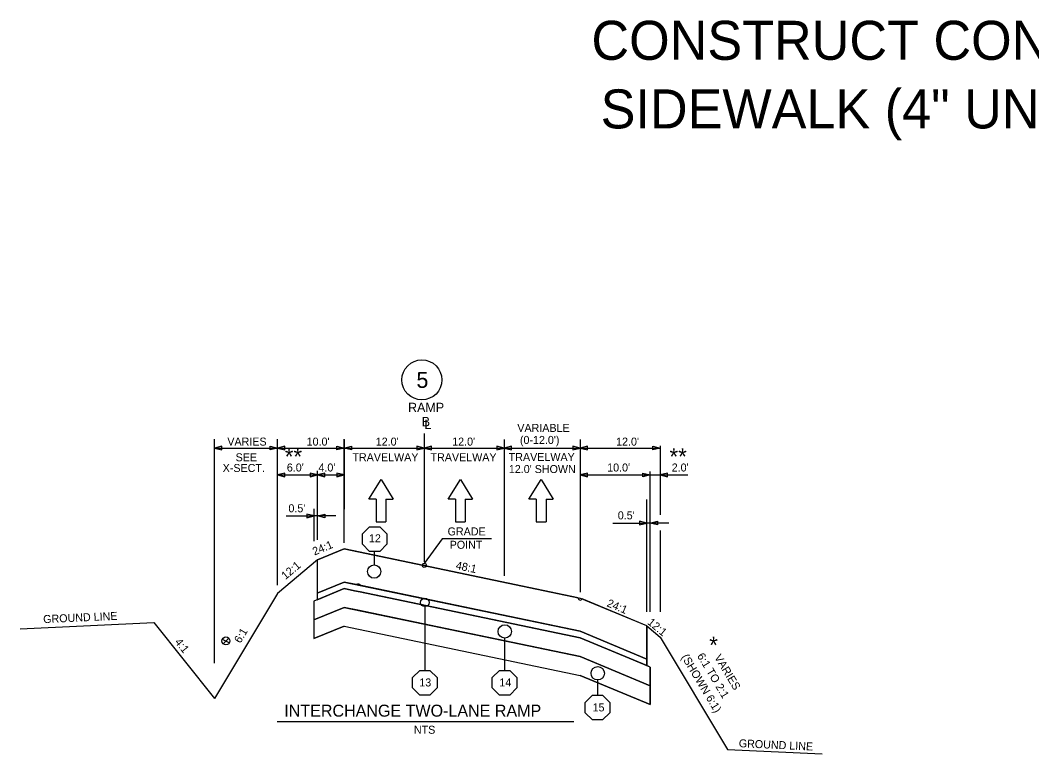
# Model space of a CAD drawing. Extents: x 4932 to 5887, y 4809 to 5473.
# Drawn here: x 5064.4 to 5216, y 5324.2 to 5434.1 of the extents above; entities that cross this region are included whole.
import ezdxf

# ---------------------------------------------------------------- set-up
doc = ezdxf.new("R2010")
doc.units = 0
for name, color, linetype in [('Level 1', 7, 'Continuous'), ('Level 2', 7, 'Continuous'), ('Level 20', 7, 'Continuous'), ('Level 25', 7, 'Continuous'), ('RD_QTY_Miscl_1', 7, 'Continuous'), ('RD_QTY_Miscl_2', 7, 'Continuous'), ('RD_QTY_Miscl_3', 7, 'Continuous'), ('RD_QTY_Miscl_4', 7, 'Continuous'), ('RD_SHT_Typical', 7, 'Continuous'), ('RD_TX_TypSect', 7, 'Continuous'), ('RD_XS_ExGround', 7, 'Continuous'), ('typical_on', 7, 'Continuous')]:
    doc.layers.add(name, color=color, linetype=linetype)

msp = doc.modelspace()

# ---------------------------------------------------------------- linework, layer by layer
at = {"layer": 'Level 2'}
for p, q in [((5108.93, 5350.24), (5108.93, 5350.24)), ((5108.93, 5350.18), (5108.93, 5350.18))]:
    msp.add_line(p, q, dxfattribs=at)
at = {"layer": 'Level 20'}
for p, q in [((5116.67, 5362.36), (5118.49, 5365.27)), ((5118.49, 5365.27), (5120.28, 5362.35)), ((5128.56, 5362.36), (5130.39, 5365.27)), ((5130.39, 5365.27), (5132.17, 5362.35)), ((5140.66, 5362.36), (5142.48, 5365.27)), ((5142.48, 5365.27), (5144.27, 5362.35)), ((5117.76, 5362.35), (5116.67, 5362.36)), ((5117.76, 5362.35), (5117.76, 5358.95)), ((5119.22, 5362.35), (5120.28, 5362.35)), ((5119.22, 5362.35), (5119.22, 5358.95)), ((5129.66, 5362.36), (5128.56, 5362.36)), ((5129.66, 5362.36), (5129.66, 5358.95)), ((5131.11, 5362.35), (5132.17, 5362.35)), ((5131.11, 5362.35), (5131.11, 5358.95)), ((5141.76, 5362.36), (5140.66, 5362.36)), ((5141.76, 5362.36), (5141.76, 5358.95)), ((5143.21, 5362.35), (5144.27, 5362.35)), ((5143.21, 5362.35), (5143.21, 5358.95)), ((5117.76, 5358.95), (5119.22, 5358.95)), ((5129.66, 5358.95), (5131.11, 5358.95)), ((5141.76, 5358.95), (5143.21, 5358.95))]:
    msp.add_line(p, q, dxfattribs=at)
at = {"layer": 'Level 25'}
for p, q in [((5127.63, 5356.42), (5124.96, 5352.72)), ((5135.02, 5356.42), (5127.63, 5356.42))]:
    msp.add_line(p, q, dxfattribs=at)
msp.add_circle((5124.6, 5380.22), 3, dxfattribs=at)
at = {"layer": 'RD_QTY_Miscl_1'}
for p, q in [((5112.95, 5354.9), (5108.95, 5353.23)), ((5108.93, 5353.21), (5108.93, 5348.25)), ((5108.93, 5348.25), (5112.95, 5349.93)), ((5112.95, 5349.93), (5114.77, 5349.55)), ((5115.48, 5349.4), (5148.34, 5342.56)), ((5158.34, 5343.34), (5148.61, 5347.39)), ((5148.34, 5342.56), (5158.34, 5338.39)), ((5158.34, 5338.39), (5158.34, 5343.34))]:
    msp.add_line(p, q, dxfattribs=at)
for points in [[(5148.05, 5347.58), (5117.52, 5353.94), (5112.95, 5354.9)], [(5108.95, 5353.23), (5108.94, 5353.21), (5108.93, 5353.21)]]:
    msp.add_lwpolyline(points, dxfattribs=at)
msp.add_circle((5117.45, 5351.5), 1, dxfattribs=at)
for centre, radius, start, end in [((5115.02, 5348.97), 0.63, 43.531, 112.936), ((5148.34, 5347.52), 0.3, 168.2335, 334.9679)]:
    msp.add_arc(centre, radius, start, end, dxfattribs=at)
at = {"layer": 'RD_QTY_Miscl_2'}
for p, q in [((5112.95, 5349.93), (5108.93, 5348.25)), ((5108.93, 5347.28), (5112.93, 5348.94)), ((5108.93, 5348.25), (5108.93, 5347.28)), ((5112.93, 5348.94), (5114.5, 5348.62)), ((5158.34, 5338.39), (5148.34, 5342.56)), ((5148.34, 5341.56), (5158.34, 5337.4)), ((5158.34, 5337.4), (5158.34, 5338.39))]:
    msp.add_line(p, q, dxfattribs=at)
for points in [[(5148.34, 5342.56), (5115.48, 5349.4), (5114.77, 5349.55), (5112.95, 5349.93)], [(5114.5, 5348.62), (5115.36, 5348.44), (5148.34, 5341.56)]]:
    msp.add_lwpolyline(points, dxfattribs=at)
at = {"layer": 'RD_QTY_Miscl_3'}
for p, q in [((5114.5, 5348.62), (5112.93, 5348.94)), ((5115.36, 5348.44), (5114.5, 5348.62)), ((5148.34, 5341.56), (5115.36, 5348.44)), ((5108.43, 5347.07), (5108.43, 5344.26)), ((5108.43, 5344.26), (5112.93, 5346.13)), ((5112.93, 5346.13), (5115, 5345.7)), ((5115, 5345.7), (5126.96, 5343.21)), ((5126.96, 5343.21), (5148.34, 5338.75)), ((5148.34, 5338.75), (5158.84, 5334.38)), ((5158.84, 5334.38), (5158.84, 5337.19))]:
    msp.add_line(p, q, dxfattribs=at)
for points in [[(5112.93, 5348.94), (5108.93, 5347.28), (5108.43, 5347.07)], [(5158.84, 5337.19), (5158.34, 5337.4), (5148.34, 5341.56)]]:
    msp.add_lwpolyline(points, dxfattribs=at)
at = {"layer": 'RD_QTY_Miscl_4'}
for p, q in [((5112.93, 5346.13), (5108.43, 5344.26)), ((5115, 5345.7), (5112.93, 5346.13)), ((5108.43, 5341.45), (5112.93, 5343.32)), ((5112.93, 5343.32), (5148.34, 5335.94)), ((5158.84, 5334.38), (5148.34, 5338.75)), ((5148.34, 5335.94), (5158.84, 5331.57)), ((5158.84, 5331.57), (5158.84, 5334.38))]:
    msp.add_line(p, q, dxfattribs=at)
for points in [[(5148.34, 5338.75), (5126.96, 5343.21), (5115, 5345.7)], [(5108.43, 5344.26), (5108.43, 5344.26), (5108.43, 5341.45)]]:
    msp.add_lwpolyline(points, dxfattribs=at)
at = {"layer": 'RD_SHT_Typical'}
for p, q in [((5108.95, 5353.23), (5112.95, 5354.9)), ((5108.95, 5353.23), (5102.96, 5348.23)), ((5108.93, 5353.22), (5108.93, 5347.28)), ((5108.93, 5348.25), (5112.95, 5349.93)), ((5102.96, 5348.23), (5093.51, 5332.49)), ((5112.93, 5348.94), (5108.43, 5347.07)), ((5112.93, 5348.94), (5148.34, 5341.56)), ((5108.43, 5347.07), (5108.43, 5341.45)), ((5158.34, 5343.34), (5148.28, 5347.53)), ((5112.93, 5346.13), (5108.43, 5344.26)), ((5112.93, 5346.13), (5148.34, 5338.75)), ((5084.43, 5343.85), (5093.51, 5332.49)), ((5112.93, 5343.32), (5108.43, 5341.45)), ((5112.93, 5343.32), (5148.34, 5335.94)), ((5158.34, 5338.39), (5148.34, 5342.56)), ((5158.34, 5343.34), (5160.34, 5341.68)), ((5158.34, 5343.34), (5158.34, 5337.4)), ((5158.84, 5337.19), (5148.34, 5341.56)), ((5160.34, 5341.68), (5170.44, 5324.84)), ((5158.84, 5334.38), (5148.34, 5338.75)), ((5158.84, 5337.19), (5158.84, 5331.57)), ((5158.84, 5331.57), (5148.34, 5335.94))]:
    msp.add_line(p, q, dxfattribs=at)
for points in [[(5112.95, 5354.9), (5148.28, 5347.53)], [(5112.95, 5349.93), (5148.34, 5342.56)]]:
    msp.add_lwpolyline(points, dxfattribs=at)
at = {"layer": 'RD_TX_TypSect'}
for p, q in [((5093.51, 5337.78), (5093.51, 5371.33)), ((5102.96, 5349.48), (5102.96, 5371.33)), ((5112.95, 5355.81), (5112.95, 5371.33)), ((5112.95, 5371.29), (5112.95, 5360.83)), ((5124.95, 5372.17), (5124.95, 5352.95)), ((5136.94, 5371.29), (5136.94, 5350.85)), ((5148.34, 5371.29), (5148.34, 5348.4)), ((5093.51, 5370), (5102.96, 5370)), ((5102.96, 5370), (5112.95, 5370)), ((5112.95, 5370), (5124.95, 5370)), ((5124.95, 5370), (5136.94, 5370)), ((5136.94, 5370), (5148.34, 5370)), ((5148.34, 5370), (5160.34, 5370)), ((5160.34, 5370.34), (5160.34, 5360.17)), ((5108.95, 5356.26), (5108.95, 5366.58)), ((5158.84, 5345.48), (5158.84, 5366.5)), ((5102.96, 5365.97), (5108.95, 5365.97)), ((5108.95, 5365.97), (5112.95, 5365.97)), ((5148.34, 5365.97), (5158.34, 5365.97)), ((5158.34, 5365.97), (5160.34, 5365.97)), ((5160.34, 5365.97), (5164.48, 5365.97)), ((5158.34, 5345.48), (5158.34, 5362.27)), ((5108.46, 5356.04), (5108.45, 5360.91)), ((5104.27, 5359.83), (5108.45, 5359.83)), ((5111.72, 5359.83), (5108.45, 5359.83)), ((5153.25, 5358.76), (5158.34, 5358.76)), ((5161.6, 5358.76), (5158.34, 5358.76)), ((5160.34, 5360.16), (5160.34, 5359.99)), ((5160.34, 5357.66), (5160.34, 5345.48)), ((5117.52, 5352.49), (5117.52, 5354.52)), ((5125.03, 5346.24), (5125.03, 5336.68)), ((5094.69, 5341.37), (5095.76, 5340.82)), ((5094.81, 5340.68), (5095.64, 5341.52)), ((5136.99, 5341.52), (5136.99, 5336.68)), ((5150.92, 5335.25), (5150.92, 5332.95)), ((5102.91, 5329.04), (5147.36, 5329.04))]:
    msp.add_line(p, q, dxfattribs=at)
for points in [[(5094.62, 5369.73), (5094.62, 5370.28), (5093.51, 5370)], [(5101.85, 5369.73), (5101.85, 5370.28), (5102.96, 5370)], [(5104.06, 5369.73), (5104.06, 5370.28), (5102.96, 5370)], [(5111.85, 5369.73), (5111.85, 5370.28), (5112.95, 5370)], [(5114.06, 5370.28), (5114.06, 5369.73), (5112.95, 5370)], [(5123.85, 5370.28), (5123.85, 5369.73), (5124.95, 5370)], [(5126.05, 5369.73), (5126.05, 5370.28), (5124.95, 5370)], [(5135.84, 5370.28), (5135.84, 5369.73), (5136.94, 5370)], [(5138.05, 5369.73), (5138.05, 5370.28), (5136.94, 5370)], [(5147.24, 5370.28), (5147.24, 5369.73), (5148.34, 5370)], [(5149.45, 5369.73), (5149.45, 5370.28), (5148.34, 5370)], [(5159.23, 5369.73), (5159.23, 5370.28), (5160.34, 5370)], [(5104.06, 5365.69), (5104.06, 5366.24), (5102.96, 5365.97)], [(5107.85, 5366.24), (5107.85, 5365.69), (5108.95, 5365.97)], [(5110.06, 5365.69), (5110.06, 5366.24), (5108.95, 5365.97)], [(5111.85, 5366.24), (5111.85, 5365.69), (5112.95, 5365.97)], [(5149.45, 5365.69), (5149.45, 5366.24), (5148.34, 5365.97)], [(5157.74, 5365.69), (5157.74, 5366.24), (5158.84, 5365.97)], [(5161.44, 5365.69), (5161.44, 5366.24), (5160.34, 5365.97)], [(5107.35, 5360.1), (5107.35, 5359.55), (5108.45, 5359.83)], [(5110.06, 5360.1), (5110.06, 5359.55), (5108.95, 5359.83)], [(5157.24, 5359.04), (5157.24, 5358.49), (5158.34, 5358.76)], [(5159.94, 5359.04), (5159.94, 5358.49), (5158.84, 5358.76)]]:
    msp.add_lwpolyline(points, close=True, dxfattribs=at)
for centre, radius in [((5124.96, 5352.42), 0.3), ((5117.45, 5351.5), 1), ((5125.05, 5346.87), 0.63), ((5137.03, 5342.52), 1), ((5095.23, 5341.1), 0.6), ((5150.96, 5336.25), 1)]:
    msp.add_circle(centre, radius, dxfattribs=at)
at = {"layer": 'RD_XS_ExGround'}
for p, q in [((5064.39, 5342.93), (5084.43, 5343.85)), ((5170.44, 5324.84), (5184.61, 5324.19))]:
    msp.add_line(p, q, dxfattribs=at)
at = {"layer": 'typical_on'}
for points in [[(5119.37, 5357.13), (5119.37, 5355.6), (5118.29, 5354.52), (5116.76, 5354.52), (5115.68, 5355.6), (5115.68, 5357.13), (5116.76, 5358.21), (5118.29, 5358.21)], [(5126.89, 5335.6), (5126.89, 5334.07), (5125.81, 5332.99), (5124.28, 5332.99), (5123.2, 5334.07), (5123.2, 5335.6), (5124.28, 5336.68), (5125.81, 5336.68)], [(5138.85, 5335.6), (5138.85, 5334.07), (5137.77, 5332.99), (5136.24, 5332.99), (5135.16, 5334.07), (5135.16, 5335.6), (5136.24, 5336.68), (5137.77, 5336.68)], [(5152.78, 5331.87), (5152.78, 5330.34), (5151.7, 5329.26), (5150.17, 5329.26), (5149.09, 5330.34), (5149.09, 5331.87), (5150.17, 5332.95), (5151.7, 5332.95)]]:
    msp.add_lwpolyline(points, close=True, dxfattribs=at)

# ---------------------------------------------------------------- texts
at = {"layer": 'Level 1'}
for s, p in [('CONSTRUCT CONCRETE ', (5150.02, 5428.18)), ('SIDEWALK (4" UNIFORM) ', (5151.4, 5417.9))]:
    msp.add_text(s, height=5.8486, rotation=0, dxfattribs=at).set_placement(p)
at = {"layer": 'Level 25'}
msp.add_text('5', height=2.4, rotation=0.0016, dxfattribs=at).set_placement((5123.79, 5379.02))
at = {"layer": 'RD_TX_TypSect'}
for s, height, rotation, p in [('RAMP', 1.4, 0.0016, (5122.53, 5375.39)), ('B ', 1.4, 0.0016, (5124.58, 5373.26)), ('L', 1.4, 0.0016, (5124.99, 5372.87)), ('VARIABLE', 1.2, 0.0016, (5138.91, 5372.42)), ('VARIES', 1.2, 0.0016, (5095.44, 5370.37)), ("10.0'", 1.2, 0.0016, (5107.33, 5370.37)), ("12.0'", 1.2, 0.0016, (5117.69, 5370.37)), ("12.0'", 1.2, 0.0016, (5129.15, 5370.37)), ("(0-12.0')", 1.2, 0.0016, (5139.3, 5370.62)), ("12.0'", 1.2, 0.0016, (5153.72, 5370.37)), ('**', 2.5, 0.0016, (5104.05, 5367.48)), ('**', 2.5, 0.0016, (5161.72, 5367.48)), ('SEE', 1.2, 0.0016, (5096.68, 5368.02)), ('TRAVELWAY', 1.2, 0.0016, (5114.19, 5368.03)), ('TRAVELWAY', 1.2, 0.0016, (5125.9, 5368.03)), ('TRAVELWAY', 1.2, 0.0016, (5137.62, 5368.06)), ('X-SECT.', 1.2, 0.0016, (5094.74, 5366.42)), ("6.0'", 1.2, 0.0016, (5104.36, 5366.49)), ("4.0'", 1.2, 0.0016, (5109.1, 5366.49)), ("12.0' SHOWN", 1.2, 0.0016, (5137.64, 5366.26)), ("10.0'", 1.2, 0.0016, (5152.38, 5366.49)), ("2.0'", 1.2, 0.0016, (5162.05, 5366.49)), ("0.5'", 1.2, 0.0016, (5104.6, 5360.38)), ("0.5'", 1.2, 0.0016, (5153.97, 5359.32)), ('GRADE', 1.2, 0.0016, (5128.46, 5356.91)), ('24:1', 1.2, 22.6207, (5108.5, 5353.89)), ('12', 1.2, 0.0016, (5116.67, 5355.88)), ('POINT', 1.2, 0.0016, (5128.77, 5354.91)), ('12:1', 1.2, 39.8072, (5104.15, 5350.22)), ('48:1', 1.2, 348.2333, (5129.61, 5351.89)), ('24:1', 1.2, 337.3818, (5152.23, 5346.32)), ('GROUND LINE', 1.2, 2.6112, (5067.86, 5343.76)), ('12:1', 1.2, 320.1955, (5158.32, 5343.72)), ('6:1', 1.2, 59.0379, (5097.4, 5340.66)), ('4:1', 1.2, 308.6614, (5087.49, 5340.9)), ('*', 2.5, 0.0016, (5167.67, 5339.24)), ('(SHOWN 6:1)', 1.2, 300.9654, (5163.46, 5338.7)), ('6:1 TO 2:1', 1.2, 300.9654, (5165.81, 5338.86)), ('VARIES', 1.2, 300.9654, (5168.39, 5338.65)), ('13', 1.2, 0.0016, (5124.22, 5334.28)), ('14', 1.2, 0.0016, (5136.21, 5334.28)), ('INTERCHANGE TWO-LANE RAMP', 1.8, 0.0016, (5103.98, 5329.75)), ('15', 1.2, 0.0016, (5150.19, 5330.54)), ('NTS', 1.2, 0.0016, (5123.41, 5327.19)), ('GROUND LINE', 1.2, 357.3921, (5172.09, 5325.18))]:
    msp.add_text(s, height=height, rotation=rotation, dxfattribs=at).set_placement(p)

doc.saveas('drawing.dxf')
